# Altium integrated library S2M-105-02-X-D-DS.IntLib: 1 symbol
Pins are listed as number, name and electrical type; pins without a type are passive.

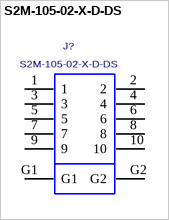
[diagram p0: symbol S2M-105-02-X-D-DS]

## S2M-105-02-X-D-DS
designator J?
2mm DOUBLE ROW SOCKET STRIP, 10 Pins, Dual Screw Down.; MANUFACTURER: SAMTEC
footprint S2M-105-02-X-D-DS
pins: 1, 2, 3, 4, 5, 6, 7, 8, 9, 10, G1, G2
